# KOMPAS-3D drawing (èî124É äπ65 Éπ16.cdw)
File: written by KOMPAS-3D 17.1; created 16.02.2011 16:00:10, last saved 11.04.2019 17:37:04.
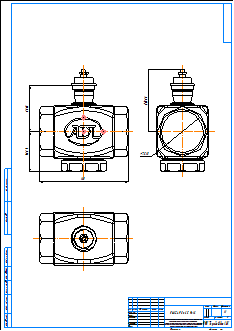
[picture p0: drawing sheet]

Title block, sheet 1: name: КМ124Р Ду65 Ру16; material: Внимание! Данный продукт является объектом авторского права ООО «Торговый Дом АДЛ». / Запрещается изменение, копирование, распространение / (в том числе путем копирования на другие сайты и ресурсы в Интернете) / или любое иное использование информации и объектов без предварительного / согласия правообладателя (ООО «Торговый Дом АДЛ»).; scale: 1:1; sheets: 1; organisation: ООО "Торговый дом АДЛ"; sheet format: A2; stored path: \\adlc.lan\data\АДЛ_ПКД\3D-модели\ADL production\Клапаны ГРАНРЕГ\Двухходовой клапан KM124P\KOMPAS 2D\КМ124Р Ду65 Ру16.cdw

Views: Спереди 1, Проекционный вид 2, Проекционный вид 3
Dimensions and other numbers on the sheet: 83,93; 72,07; 160; 112,93; 75,18; 1:1; 1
